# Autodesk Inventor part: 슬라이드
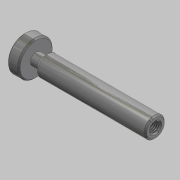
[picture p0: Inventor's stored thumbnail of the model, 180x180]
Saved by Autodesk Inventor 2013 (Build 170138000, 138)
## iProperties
Created: 2015-12
Part Number: 슬라이드
Document SubType Name: Modeling
Designer: mdu
Density: 8.08 g/cm^3
Material: 스테인리스강
Mass: 121.271 g
Surface Area: 52.6604 cm^2
Volume: 15.0088 cm^3
Author: mdu
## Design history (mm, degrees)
sketch "스케치1"
  geometry: L1 (-45, 0)-(45, 0); L2 (-45, 0)-(-45, 12); L3 (-45, 12)-(-37, 12); L4 (-37, 12)-(-37, 4); L5 (-37, 4)-(-32, 4); L6 (-32, 4)-(-29, 7); L7 (-29, 7)-(45, 7); L8 (45, 7)-(45, 0); 2 further points
  constraints: 16 end point, 4 parallel, 2 perpendicular, 1 coincident, 1 horizontal, 1 midpoint
  dimensions: "d0" = 90 distance of L1.start L1.end; "d1" = 24 diameter of L3 L1; "d2" = 14 diameter of L7 L1; "d3" = 8 diameter of L5 L1; "d4" = 8 distance of L2.end L3.end; "d5" = 5 distance of L4.end L5.end; "d6" = 135 deg angle of L6 L5
revolve "회전1" sketch "스케치1" stored, may be unused: angle "d7" = 90 deg
chamfer "모따기1" distance "d8" = 1; stored, may be unused: second distance "d9" = 2, angle "d10" = 45 deg
hole "구멍1" diameter "d13" = 6.647; stored, may be unused: countersink angle "d17" = 90 deg, drill point angle "d19" = 118 deg; dims "d11" = 10, "d12" = 10, "d14" = 9, "d15" = 4, "d16" = 2, "d18" = 12
chamfer "모따기2" distance "d20" = 1; stored, may be unused: second distance "d21" = 2, angle "d22" = 45 deg
node "솔리드1"
